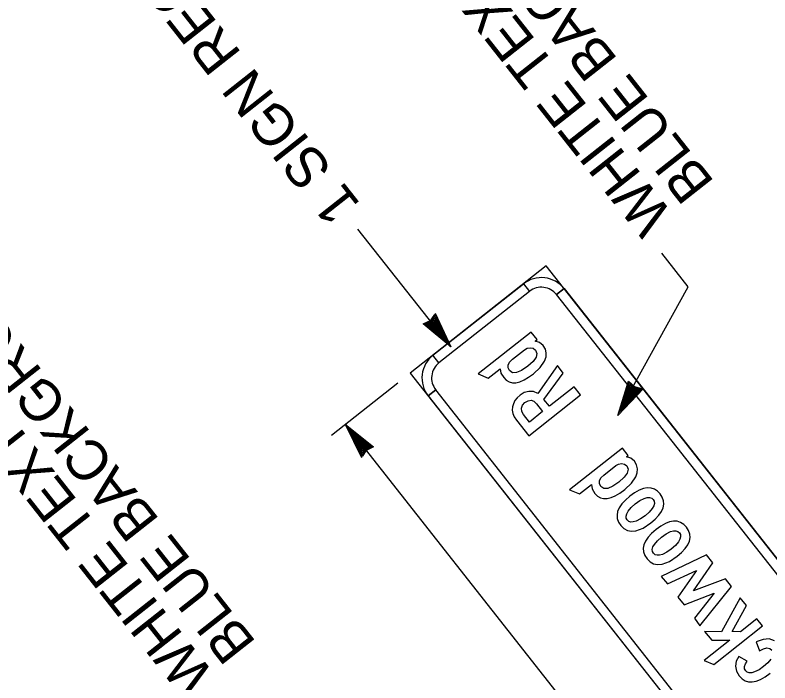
# Model space of a CAD drawing. Extents: x 672438 to 673980, y 1673259 to 1674850.
# Drawn here: x 673647.2 to 673725.7, y 1673427.3 to 1673496.8 of the extents above; entities that cross this region are included whole.
import ezdxf

# ---------------------------------------------------------------- set-up
doc = ezdxf.new("R2010")
doc.units = 0
doc.layers.add('C-ANNO-SYMB', color=7, linetype='Continuous')
doc.layers.add('Level 1', color=7, linetype='Continuous')

msp = doc.modelspace()

# ---------------------------------------------------------------- linework, layer by layer
at = {"layer": 'C-ANNO-SYMB'}
for p, q in [((673702.406, 1673470.689), (673688.27, 1673459.545)), ((673780.412, 1673371.74), (673702.406, 1673470.689)), ((673690.626, 1673461.402), (673700.05, 1673468.831)), ((673700.05, 1673468.831), (673700.669, 1673468.046)), ((673700.05, 1673468.831), (673700.669, 1673468.046)), ((673700.669, 1673468.046), (673691.245, 1673460.617)), ((673700.669, 1673468.046), (673700.669, 1673468.046)), ((673700.669, 1673468.046), (673700.669, 1673468.046)), ((673703.478, 1673467.714), (673704.263, 1673468.333)), ((673704.263, 1673468.333), (673703.478, 1673467.714)), ((673704.263, 1673468.333), (673778.555, 1673374.095)), ((673777.77, 1673373.476), (673703.478, 1673467.714)), ((673691.245, 1673460.617), (673690.626, 1673461.402)), ((673691.245, 1673460.617), (673690.626, 1673461.402)), ((673691.245, 1673460.617), (673690.626, 1673461.402)), ((673688.27, 1673459.545), (673766.277, 1673360.596)), ((673690.127, 1673457.189), (673690.913, 1673457.808)), ((673690.913, 1673457.808), (673690.127, 1673457.189)), ((673690.913, 1673457.808), (673690.913, 1673457.808)), ((673690.913, 1673457.808), (673690.913, 1673457.808)), ((673765.205, 1673363.571), (673690.913, 1673457.808)), ((673690.127, 1673457.189), (673764.42, 1673362.952))]:
    msp.add_line(p, q, dxfattribs=at)
for points in [[(673701.45, 1673463.027), (673700.846, 1673463.793), (673695.344, 1673459.456), (673696.365, 1673459.018), (673697.613, 1673460.003), (673697.7, 1673459.549), (673697.981, 1673459.077), (673698.249, 1673458.806), (673698.548, 1673458.63), (673698.884, 1673458.543), (673699.254, 1673458.55), (673699.66, 1673458.646), (673700.101, 1673458.835), (673700.577, 1673459.115), (673701.083, 1673459.484), (673701.786, 1673460.138), (673702.236, 1673460.797), (673702.391, 1673461.233), (673702.416, 1673461.65), (673702.316, 1673462.047), (673702.087, 1673462.426), (673701.717, 1673462.735), (673701.261, 1673462.878), (673701.45, 1673463.027)], [(673700.148, 1673461.975), (673700.43, 1673462.135), (673700.736, 1673462.191), (673701.055, 1673462.133), (673701.297, 1673461.937), (673701.439, 1673461.591), (673701.349, 1673461.196), (673701.034, 1673460.753), (673700.487, 1673460.258), (673699.852, 1673459.82), (673699.322, 1673459.598), (673698.905, 1673459.594), (673698.595, 1673459.807), (673698.445, 1673460.096), (673698.446, 1673460.391), (673698.597, 1673460.688), (673698.898, 1673460.989), (673700.148, 1673461.975)], [(673705.974, 1673457.279), (673705.307, 1673458.124), (673702.741, 1673456.101), (673702.173, 1673456.821), (673704.184, 1673459.55), (673703.574, 1673460.323), (673701.534, 1673457.445), (673701.082, 1673457.63), (673700.584, 1673457.65), (673700.125, 1673457.523), (673699.693, 1673457.263), (673699.387, 1673456.985), (673699.151, 1673456.686), (673698.987, 1673456.371), (673698.892, 1673456.04), (673698.873, 1673455.685), (673698.938, 1673455.333), (673699.083, 1673454.985), (673699.311, 1673454.642), (673700.583, 1673453.029), (673705.974, 1673457.279)], [(673702.031, 1673455.541), (673700.656, 1673454.458), (673700.033, 1673455.249), (673699.862, 1673455.564), (673699.826, 1673455.895), (673699.933, 1673456.21), (673700.18, 1673456.482), (673700.515, 1673456.676), (673700.825, 1673456.72), (673701.117, 1673456.615), (673701.386, 1673456.358), (673702.031, 1673455.541)], [(673710.941, 1673450.988), (673710.337, 1673451.755), (673704.835, 1673447.417), (673705.856, 1673446.979), (673707.104, 1673447.964), (673707.191, 1673447.51), (673707.472, 1673447.038), (673707.74, 1673446.767), (673708.039, 1673446.591), (673708.375, 1673446.504), (673708.744, 1673446.511), (673709.151, 1673446.607), (673709.592, 1673446.796), (673710.068, 1673447.076), (673710.574, 1673447.446), (673711.277, 1673448.099), (673711.727, 1673448.758), (673711.882, 1673449.194), (673711.907, 1673449.611), (673711.807, 1673450.008), (673711.578, 1673450.387), (673711.208, 1673450.696), (673710.751, 1673450.839), (673710.941, 1673450.988)], [(673709.639, 1673449.936), (673709.921, 1673450.096), (673710.227, 1673450.152), (673710.546, 1673450.094), (673710.788, 1673449.898), (673710.93, 1673449.552), (673710.84, 1673449.157), (673710.525, 1673448.714), (673709.978, 1673448.219), (673709.342, 1673447.782), (673708.813, 1673447.559), (673708.396, 1673447.555), (673708.086, 1673447.768), (673707.936, 1673448.057), (673707.936, 1673448.352), (673708.088, 1673448.649), (673708.389, 1673448.95), (673709.639, 1673449.936)], [(673711.099, 1673446.74), (673710.637, 1673446.339), (673710.271, 1673445.944), (673710.008, 1673445.554), (673709.839, 1673445.171), (673709.774, 1673444.794), (673709.804, 1673444.423), (673709.936, 1673444.058), (673710.164, 1673443.702), (673710.485, 1673443.386), (673710.852, 1673443.189), (673711.266, 1673443.115), (673711.724, 1673443.159), (673712.483, 1673443.44), (673713.284, 1673443.967), (673713.755, 1673444.372), (673714.123, 1673444.768), (673714.396, 1673445.156), (673714.564, 1673445.537), (673714.639, 1673445.91), (673714.611, 1673446.276), (673714.485, 1673446.635), (673714.26, 1673446.985), (673713.974, 1673447.282), (673713.655, 1673447.489), (673713.307, 1673447.6), (673712.924, 1673447.618), (673712.517, 1673447.54), (673712.074, 1673447.367), (673711.604, 1673447.101), (673711.099, 1673446.74)], [(673711.668, 1673445.962), (673712.148, 1673446.298), (673712.599, 1673446.528), (673712.904, 1673446.616), (673713.164, 1673446.627), (673713.377, 1673446.56), (673713.542, 1673446.417), (673713.644, 1673446.221), (673713.658, 1673445.999), (673713.592, 1673445.751), (673713.435, 1673445.478), (673713.119, 1673445.094), (673712.684, 1673444.709), (673712.213, 1673444.38), (673711.767, 1673444.163), (673711.466, 1673444.075), (673711.207, 1673444.067), (673710.996, 1673444.134), (673710.829, 1673444.278), (673710.732, 1673444.469), (673710.715, 1673444.688), (673710.782, 1673444.932), (673710.928, 1673445.203), (673711.246, 1673445.584), (673711.668, 1673445.962)], [(673713.829, 1673443.276), (673713.368, 1673442.876), (673713.001, 1673442.481), (673712.739, 1673442.091), (673712.569, 1673441.708), (673712.505, 1673441.33), (673712.534, 1673440.96), (673712.666, 1673440.595), (673712.894, 1673440.239), (673713.215, 1673439.922), (673713.582, 1673439.726), (673713.997, 1673439.652), (673714.455, 1673439.696), (673715.214, 1673439.977), (673716.015, 1673440.504), (673716.485, 1673440.909), (673716.854, 1673441.304), (673717.126, 1673441.693), (673717.295, 1673442.074), (673717.37, 1673442.447), (673717.341, 1673442.813), (673717.215, 1673443.171), (673716.99, 1673443.522), (673716.705, 1673443.819), (673716.385, 1673444.025), (673716.037, 1673444.137), (673715.655, 1673444.154), (673715.247, 1673444.077), (673714.804, 1673443.904), (673714.334, 1673443.638), (673713.829, 1673443.276)], [(673714.398, 1673442.499), (673714.878, 1673442.835), (673715.33, 1673443.065), (673715.635, 1673443.153), (673715.894, 1673443.164), (673716.107, 1673443.097), (673716.272, 1673442.953), (673716.375, 1673442.758), (673716.389, 1673442.536), (673716.322, 1673442.288), (673716.165, 1673442.015), (673715.849, 1673441.631), (673715.414, 1673441.245), (673714.944, 1673440.917), (673714.497, 1673440.7), (673714.196, 1673440.612), (673713.937, 1673440.604), (673713.727, 1673440.67), (673713.559, 1673440.815), (673713.462, 1673441.006), (673713.445, 1673441.225), (673713.513, 1673441.469), (673713.659, 1673441.74), (673713.976, 1673442.121), (673714.398, 1673442.499)], [(673726.157, 1673431.724), (673725.608, 1673431.909), (673724.966, 1673431.867), (673724.231, 1673431.6), (673724.578, 1673430.683), (673725.009, 1673430.888), (673725.367, 1673430.968), (673725.66, 1673430.915), (673725.885, 1673430.735)], [(673725.769, 1673429.798), (673725.451, 1673429.413), (673725.018, 1673429.028), (673724.545, 1673428.701), (673724.09, 1673428.482), (673723.792, 1673428.394), (673723.535, 1673428.382), (673723.327, 1673428.445), (673723.161, 1673428.587), (673723.045, 1673428.813), (673723.034, 1673429.055), (673723.129, 1673429.318), (673723.326, 1673429.599), (673722.449, 1673430.1), (673722.174, 1673429.613), (673722.093, 1673429.09), (673722.203, 1673428.563), (673722.494, 1673428.062), (673722.783, 1673427.762), (673723.103, 1673427.561), (673723.455, 1673427.454), (673723.837, 1673427.441), (673724.254, 1673427.524), (673724.699, 1673427.701), (673725.177, 1673427.973), (673725.687, 1673428.34)]]:
    msp.add_lwpolyline(points, dxfattribs=at)
for points in [[(673718.382, 1673433.278), (673721.679, 1673437.358), (673721.044, 1673438.162), (673717.742, 1673436.917), (673719.737, 1673439.821), (673719.09, 1673440.641), (673714.353, 1673438.388), (673715.018, 1673437.643), (673718.038, 1673439.035), (673716.103, 1673436.267), (673716.744, 1673435.453), (673719.884, 1673436.658), (673717.829, 1673434.076)], [(673724.912, 1673433.256), (673724.329, 1673433.996), (673722.611, 1673432.641), (673721.752, 1673432.669), (673723.24, 1673435.377), (673722.598, 1673436.191), (673720.649, 1673432.664), (673718.864, 1673432.666), (673719.627, 1673431.797), (673721.508, 1673431.772), (673718.832, 1673429.662), (673719.832, 1673429.251)]]:
    msp.add_lwpolyline(points, close=True, dxfattribs=at)
for centre, radius, start, end in [((673701.907, 1673466.476), 3, 38.2506, 128.25081), ((673701.907, 1673466.476), 2, 38.2506, 128.25081), ((673692.483, 1673459.046), 3, 128.25054, 218.25075), ((673692.483, 1673459.046), 2, 128.25054, 218.25075)]:
    msp.add_arc(centre, radius, start, end, dxfattribs=at)
at = {"layer": 'Level 1'}
for p, q in [((673692.476, 1673462.277), (673682.818, 1673474.528)), ((673690.337, 1673464.966), (673690.824, 1673465.626)), ((673690.824, 1673465.626), (673690.756, 1673465.409)), ((673690.845, 1673465.773), (673692.476, 1673462.277)), ((673689.616, 1673464.658), (673690.384, 1673465.034)), ((673689.765, 1673464.637), (673690.337, 1673464.966)), ((673690.064, 1673464.629), (673690.777, 1673465.295)), ((673690.196, 1673464.763), (673690.777, 1673465.295)), ((673690.199, 1673464.668), (673690.714, 1673465.117)), ((673690.609, 1673465.038), (673690.331, 1673464.668)), ((673690.342, 1673464.609), (673690.672, 1673464.956)), ((673690.384, 1673465.034), (673690.699, 1673465.269)), ((673690.468, 1673464.571), (673690.62, 1673464.849)), ((673690.613, 1673464.68), (673690.609, 1673465.038)), ((673690.62, 1673464.849), (673690.88, 1673464.327)), ((673690.672, 1673464.956), (673691.168, 1673463.985)), ((673690.699, 1673465.269), (673690.893, 1673465.58)), ((673690.714, 1673465.117), (673691.429, 1673463.592)), ((673690.756, 1673465.409), (673690.851, 1673465.415)), ((673690.777, 1673465.295), (673691.759, 1673463.151)), ((673690.777, 1673465.295), (673691.881, 1673463.077)), ((673690.851, 1673465.415), (673692.214, 1673462.542)), ((673690.893, 1673465.58), (673692.126, 1673462.705)), ((673692.476, 1673462.277), (673689.616, 1673464.658)), ((673692.245, 1673462.499), (673689.765, 1673464.637)), ((673689.933, 1673464.63), (673690.196, 1673464.763)), ((673691.977, 1673462.856), (673689.933, 1673464.63)), ((673691.759, 1673463.151), (673690.064, 1673464.629)), ((673691.881, 1673463.077), (673690.199, 1673464.668)), ((673690.331, 1673464.668), (673691.078, 1673464.146)), ((673691.429, 1673463.592), (673690.342, 1673464.609)), ((673691.168, 1673463.985), (673690.468, 1673464.571)), ((673690.546, 1673464.6), (673690.613, 1673464.68)), ((673690.88, 1673464.327), (673690.546, 1673464.6)), ((673691.078, 1673464.146), (673691.173, 1673463.891)), ((673709.865, 1673455.15), (673710.981, 1673458.7)), ((673709.983, 1673455.449), (673711.018, 1673458.555)), ((673710.981, 1673458.7), (673711.621, 1673458.133)), ((673711.018, 1673458.555), (673711.54, 1673458.151)), ((673686.983, 1673458.51), (673680.079, 1673453.067)), ((673712.519, 1673457.95), (673709.865, 1673455.15)), ((673712.15, 1673457.845), (673710.01, 1673455.494)), ((673712.319, 1673457.869), (673710.127, 1673455.637)), ((673710.211, 1673455.833), (673711.076, 1673458.397)), ((673710.379, 1673456.005), (673711.212, 1673458.165)), ((673712.011, 1673457.869), (673710.379, 1673456.005)), ((673710.401, 1673456.146), (673711.125, 1673458.275)), ((673712.011, 1673457.869), (673710.401, 1673456.146)), ((673710.684, 1673456.619), (673711.212, 1673458.011)), ((673711.823, 1673457.859), (673710.684, 1673456.619)), ((673710.948, 1673457.009), (673711.225, 1673457.879)), ((673711.658, 1673457.837), (673710.948, 1673457.009)), ((673711.262, 1673458.044), (673711.063, 1673457.154)), ((673711.076, 1673458.397), (673711.298, 1673458.204)), ((673711.125, 1673458.275), (673712.011, 1673457.869)), ((673711.54, 1673457.845), (673711.155, 1673457.406)), ((673711.155, 1673457.406), (673711.28, 1673457.818)), ((673711.212, 1673458.165), (673711.823, 1673457.859)), ((673711.212, 1673458.011), (673711.658, 1673457.837)), ((673711.225, 1673457.879), (673711.54, 1673457.845)), ((673711.71, 1673457.926), (673711.262, 1673458.044)), ((673711.28, 1673457.818), (673711.381, 1673457.787)), ((673711.298, 1673458.204), (673712.011, 1673457.869)), ((673711.381, 1673457.787), (673711.71, 1673457.926)), ((673711.54, 1673458.151), (673712.336, 1673457.951)), ((673711.621, 1673458.133), (673711.958, 1673457.931)), ((673711.958, 1673457.931), (673712.319, 1673457.869)), ((673712.108, 1673457.931), (673712.15, 1673457.845)), ((673711.063, 1673457.154), (673710.863, 1673456.969)), ((673710.193, 1673455.596), (673710.786, 1673456.28)), ((673710.786, 1673456.28), (673710.211, 1673455.833)), ((673710.863, 1673456.969), (673710.651, 1673456.514)), ((673710.651, 1673456.514), (673710.983, 1673456.865)), ((673683.227, 1673450.744), (673681.523, 1673454.206)), ((673681.523, 1673454.206), (673684.432, 1673451.884)), ((673715.993, 1673410.551), (673681.557, 1673454.232)), ((673681.883, 1673453.785), (673681.759, 1673453.988)), ((673681.759, 1673453.988), (673684.283, 1673451.903)), ((673683.213, 1673451.102), (673681.791, 1673453.946)), ((673681.791, 1673453.946), (673681.82, 1673453.739)), ((673681.82, 1673453.739), (673682.245, 1673452.939)), ((673683.174, 1673450.936), (673681.883, 1673453.785)), ((673682.245, 1673452.939), (673682.035, 1673453.637)), ((673682.035, 1673453.637), (673684.115, 1673451.905)), ((673683.285, 1673451.223), (673682.134, 1673453.418)), ((673682.134, 1673453.418), (673683.85, 1673451.863)), ((673683.285, 1673451.223), (673682.258, 1673453.346)), ((673682.258, 1673453.346), (673683.983, 1673451.904)), ((673682.859, 1673452.619), (673682.512, 1673452.98)), ((673682.512, 1673452.98), (673682.719, 1673452.545)), ((673683.343, 1673451.402), (673682.597, 1673452.912)), ((673682.597, 1673452.912), (673683.705, 1673451.918)), ((673682.96, 1673452.365), (673682.859, 1673452.619)), ((673683.383, 1673451.565), (673682.866, 1673452.525)), ((673682.866, 1673452.525), (673683.578, 1673451.953)), ((673683.718, 1673451.859), (673682.96, 1673452.365)), ((673683.432, 1673451.672), (673683.162, 1673452.189)), ((673683.162, 1673452.189), (673683.501, 1673451.923)), ((673683.718, 1673451.562), (673683.245, 1673450.891)), ((673683.983, 1673451.904), (673683.285, 1673451.223)), ((673683.855, 1673451.767), (673683.285, 1673451.223)), ((673683.85, 1673451.863), (673683.343, 1673451.402)), ((673683.672, 1673451.492), (673683.362, 1673451.251)), ((673683.705, 1673451.918), (673683.383, 1673451.565)), ((673683.578, 1673451.953), (673683.432, 1673451.672)), ((673683.501, 1673451.923), (673683.436, 1673451.841)), ((673683.436, 1673451.841), (673683.447, 1673451.484)), ((673683.447, 1673451.484), (673683.718, 1673451.859)), ((673684.432, 1673451.884), (673683.672, 1673451.492)), ((673684.283, 1673451.903), (673683.718, 1673451.562)), ((673684.115, 1673451.905), (673683.855, 1673451.767)), ((673683.362, 1673451.251), (673683.174, 1673450.936)), ((673683.308, 1673451.11), (673683.213, 1673451.102))]:
    msp.add_line(p, q, dxfattribs=at)
msp.add_lwpolyline([(673711.002, 1673457.358), (673717.165, 1673468.535), (673714.419, 1673472.018)], dxfattribs=at)

# ---------------------------------------------------------------- texts
for s, p in [('BLUE BACKGROUND', (673719.992, 1673479.372)), ('1 SIGN REQUIRED', (673683.175, 1673477.067)), ('WHITE TEXT ON', (673715.698, 1673475.987)), ('BLUE BACKGROUND', (673672.325, 1673431.507)), ('WHITE TEXT ON', (673668.031, 1673428.122)), ('2 SIGNS REQUIRED', (673656.723, 1673411.09))]:
    msp.add_text(s, height=4.2, rotation=128.25054, dxfattribs=at).set_placement(p)

doc.saveas('drawing.dxf')
